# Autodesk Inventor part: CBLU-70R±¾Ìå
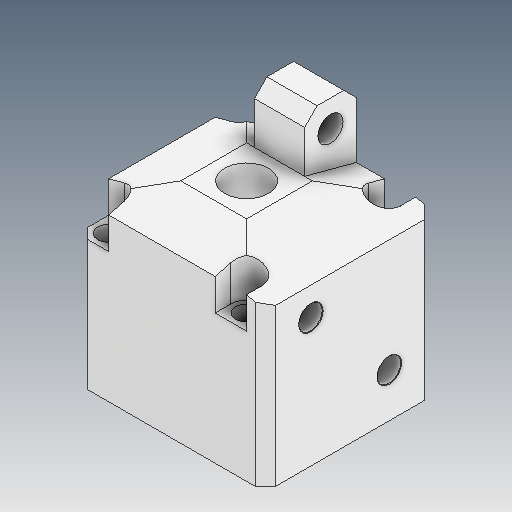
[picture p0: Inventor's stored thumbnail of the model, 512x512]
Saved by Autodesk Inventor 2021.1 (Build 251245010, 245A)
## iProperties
Created: 2021-05
Part Number: CBLU-70R±¾Ìå
Material: Ogólny
Document SubType Name: Modeling
Designer: user
Density: 1 g/cm^3
Appearance: Domyślna
Author: user
Revision Number: ÈÎºÎ
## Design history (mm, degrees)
feature "ÊäÈë1"
feature "ÊäÈë2"
node "Bryła1"
node "Bryła2"
